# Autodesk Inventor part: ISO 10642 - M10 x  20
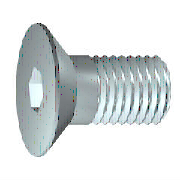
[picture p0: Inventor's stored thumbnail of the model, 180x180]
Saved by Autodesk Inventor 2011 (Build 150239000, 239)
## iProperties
Created: 2010-02
Part Number: ISO 10642 - M10 x  20
Material: Steel
Description: Hexagon Socket Countersunk Head Screw-1 - Product grade A
Document SubType Name: Modeling
Standard: ISO 10642
Designer: R. Koolhoven
Standard Revision: Second edition 2004-03-01
Standards Organization: ISO
Language: en-US
Size Designation: M10 x  20
Categories: <MemberInstance><Categories><Category DisplayName="Fasteners" InternalName="e4da775c-781d-43d5-af7c-5136215cf5a6" Mnemonic="FSTN"><Category DisplayName="Bolts"
Density: 7.85 g/cm^3
IsCustomPart: 0
Author: R. Koolhoven
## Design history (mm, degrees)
workplane "Work Plane1"
revolve "Body" stored, may be unused: angle "d13" = 90 deg
sketch "Sketch2"
  geometry: L1 (0, -13.454)-(0, 13.454) reference; L2 (-13.454, 0)-(13.454, 0) reference; L3 (3.464, 0)-(1.732, -3); L4 (1.732, -3)-(-1.732, -3); L5 (-1.732, -3)-(-3.464, 0); L6 (-3.464, 0)-(-1.732, 3); L7 (-1.732, 3)-(1.732, 3); L8 (1.732, 3)-(3.464, 0); A1 r 3.464 centre (0, 0) between (0, 3.464) and (3.464, 0) reference; 2 further points
  constraints: 12 end point, 2 coincident, 2 point on circle, 2 point on line, 12 other
extrude "Slot" join sketch "Sketch2" taper "d14" = 0 deg; stored distance "d30" = 10
body "Solid1"
feature "Thread" dims "d15" = 9 (= GEL), "d16" = 0
chamfer "Chamfer1" distance "d17" = 0.92018 (= -0.5 x SPD + 0.5 x GD); stored, may be unused: second distance "d18" = 0.92018 (= GUL), angle "d39" = 45 deg
sketch "Sketch1"
  geometry: L1 (20, 0)-(20, 5); L2 (20, 5)-(11, 5); L3 (11, 5)-(10.08, 5); L4 (0, 9.61)-(0, 3.464); L5 (0, 3.464)-(4.18, 3.464); L6 (4.18, 3.464)-(6.18, 0); L7 (6.18, 0)-(20, 0); L8 (0, 9.61)-(1.59, 9.61); L9 (1.59, 9.61)-(6.2, 5); L10 (10.08, 5)-(6.2, 5); L11 (11, 5)-(6.2, 5); L12 (6.2, 5)-(6.2, 5); L13 (-4, 0)-(24, 0) reference; L14 (0, -1.922)-(0, 11.532) reference
  constraints: 24 end point, 4 collinear, 3 parallel
  dimensions: "d0" = 20 distance between parallel lines of L4 L1 (= NLG); "d1" = 9 distance from line of L2.end L1 (= GEL); "d2" = 4.18 distance from line of L5.end L4 (= INTI); "d3" = 10 diameter of L2 L7 (= GD); "d6" = 6.2 distance from line of L9.end L4 (= KOH); "d7" = 45 deg angle of L9 L7 (= 0.5 x SEWI); "d8" = 6.9282 diameter of L5 L7 (= 1.1547 x SW); "d9" = 60 deg angle of L6 L7; "d10" = 19.22 diameter of L8 L7 (= KOD); "d11" = 10 diameter of L10 L7 (= BDM); "d12" = 0.92018 distance of L3.end L2.end (= GAL)
other parameters: "NLG" = 20 [user parameter; used in 1 equation term], "INTI" = 4.18 [user parameter; used in 1 equation term], "GEL" = 9 [user parameter; used in 2 equation terms], "GAL" = 0.92018 (= 0.61345 x PTC) [user parameter; used in 1 equation term], "KOH" = 6.2 [user parameter; used in 1 equation term], "KOD" = 19.22 [user parameter; used in 1 equation term], "GUL" = 0.92018 (= 0.61345 x PTC) [user parameter; used in 1 equation term], "SPD" = 8.15965 (= NND - 1.2269 x PTC) [user parameter; used in 1 equation term], "BDM" = 10 (= NND) [user parameter; used in 1 equation term], "GD" = 10 (= NND) [user parameter; used in 2 equation terms], "SEWI" = 90 deg [user parameter; used in 1 equation term], "d20" = 0, "SW" = 6 [user parameter; used in 1 equation term], "d43" = 0, "d44" = 0, "TOA" = 30 deg [user parameter], "GD1" = 8.15965 (= THREADDIA - 1.2269 x PTC) [user parameter], "EPV" = 11.2 [user parameter], "TPU" = 6.66667 (computed from PTC) [user parameter], "PTC" = 1.5 [user parameter; used in 5 equation terms], "E0" = 6.93 [user parameter], "THREADDESC" = 12.345 [user parameter]
